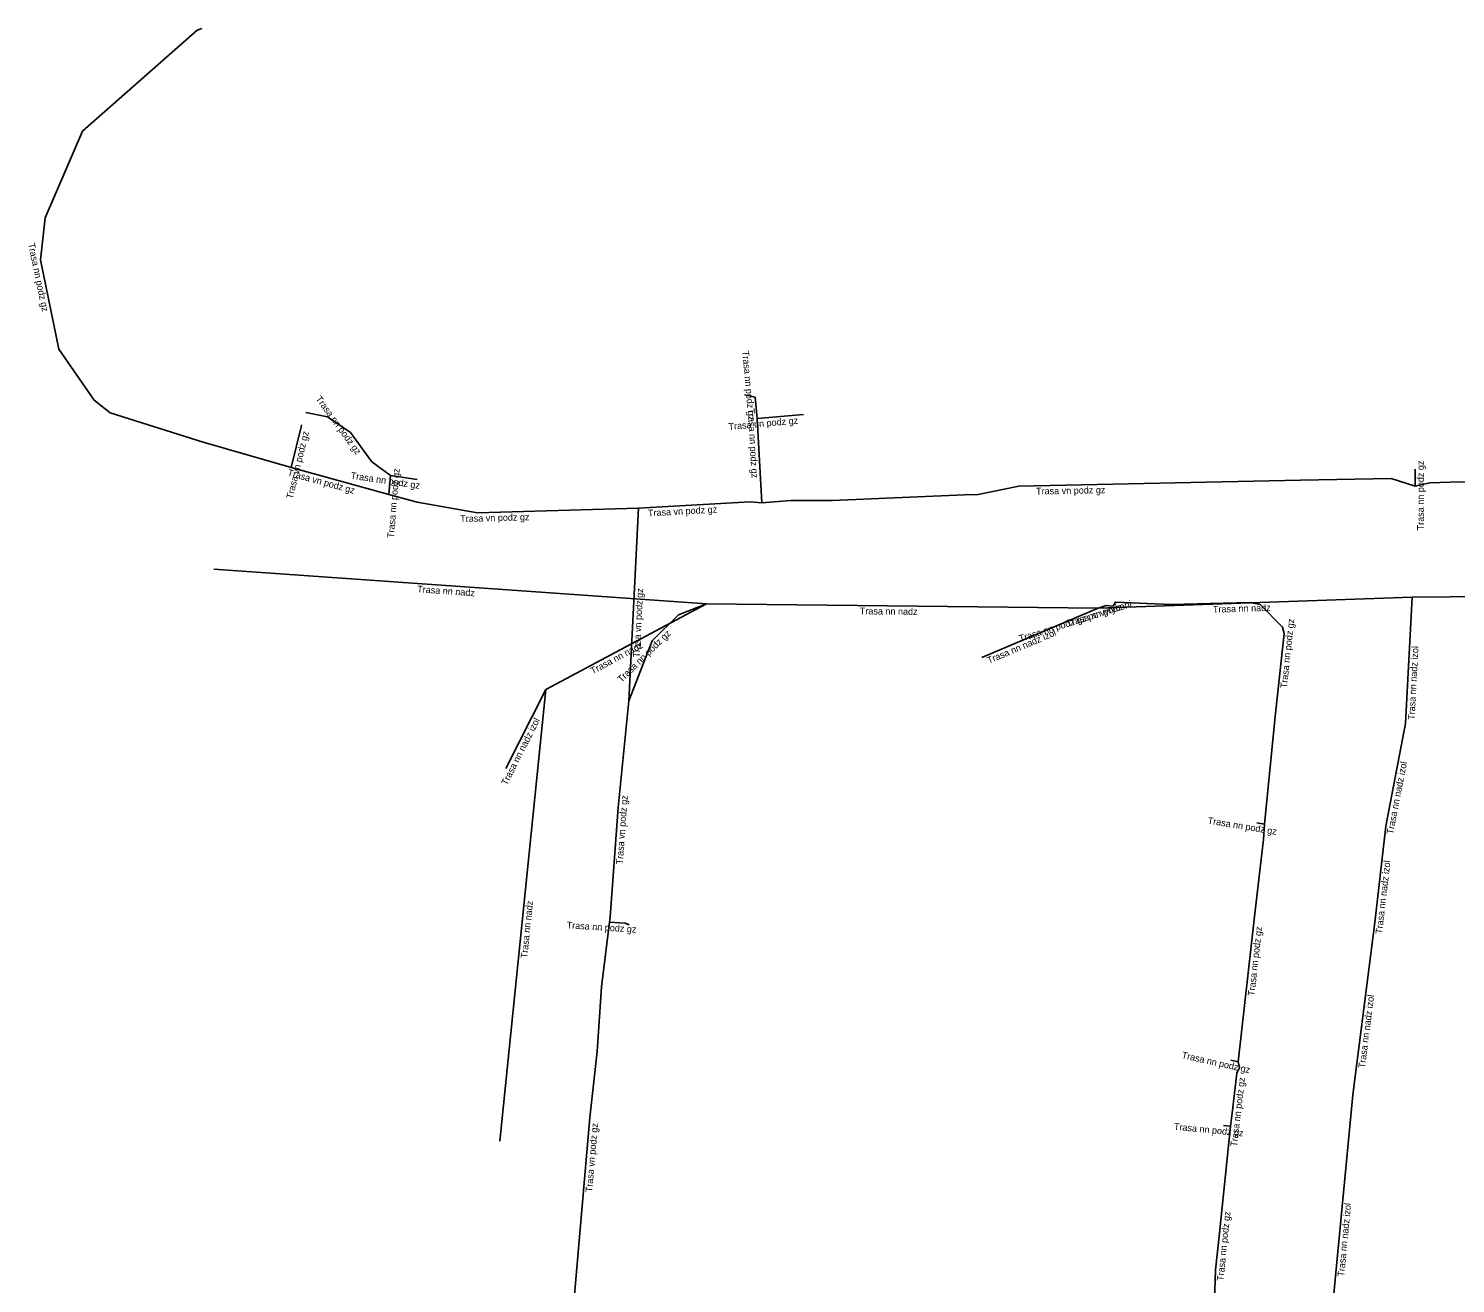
# Model space of a CAD drawing. Extents: x -772942 to -772530, y -1033745 to -1033298.
# Drawn here: x -772776.3 to -772670.7, y -1033402.1 to -1033309.2 of the extents above; entities that cross this region are included whole.
import ezdxf

# ---------------------------------------------------------------- set-up
doc = ezdxf.new("R2010")
doc.units = 0
for name, color, linetype in [('Popiskový text - Ostatní atributy Trasy', 7, 'Continuous'), ('Spojnice NN', 7, 'Continuous'), ('Spojnice VN', 7, 'Continuous')]:
    doc.layers.add(name, color=color, linetype=linetype)

msp = doc.modelspace()

# ---------------------------------------------------------------- linework, layer by layer
at = {"layer": 'Spojnice NN'}
for points in [[(-772756.83, -1033341.72), (-772763.36, -1033339.83), (-772770.24, -1033337.68), (-772771.43, -1033336.73), (-772774.03, -1033332.96), (-772775.4, -1033326.36), (-772775.05, -1033323.25), (-772772.27, -1033316.82), (-772763.8, -1033309.35), (-772763.46, -1033309.23)], [(-772722.36, -1033338.1), (-772722.51, -1033336.52), (-772723.29, -1033336.35)], [(-772749.5, -1033342.32), (-772750.87, -1033341.3), (-772752.45, -1033339.13), (-772754.15, -1033337.97), (-772755.76, -1033337.64)], [(-772722.36, -1033338.1), (-772718.93, -1033337.79)], [(-772722.01, -1033344.32), (-772722.36, -1033338.1)], [(-772749.5, -1033342.32), (-772749.61, -1033343.7)], [(-772747.53, -1033342.61), (-772749.5, -1033342.32)], [(-772673.68, -1033343.11), (-772673.68, -1033341.85)], [(-772762.57, -1033349.25), (-772726.12, -1033351.81)], [(-772726.12, -1033351.81), (-772738.01, -1033358.15)], [(-772731.86, -1033358.99), (-772730.14, -1033354.54), (-772728.18, -1033352.61), (-772726.12, -1033351.81)], [(-772726.12, -1033351.81), (-772697.12, -1033352.12)], [(-772697.12, -1033352.12), (-772673.89, -1033351.31)], [(-772684.83, -1033368.1), (-772684.03, -1033360.15), (-772683.38, -1033354), (-772683.48, -1033353.53), (-772685.15, -1033351.85), (-772685.91, -1033351.7), (-772691.73, -1033351.86), (-772695.85, -1033351.68), (-772696.01, -1033351.99)], [(-772674.39, -1033360.65), (-772673.89, -1033351.31)], [(-772656.87, -1033351.16), (-772673.89, -1033351.31)], [(-772705.74, -1033355.77), (-772697.12, -1033352.12)], [(-772696.01, -1033351.99), (-772696.55, -1033351.94), (-772697.12, -1033352.12)], [(-772696.01, -1033351.99), (-772696.55, -1033351.94), (-772697.12, -1033352.12)], [(-772741.4, -1033391.57), (-772738.01, -1033358.15)], [(-772740.96, -1033363.99), (-772738.01, -1033358.15)], [(-772675.85, -1033368.26), (-772674.39, -1033360.65)], [(-772686.77, -1033385.7), (-772685.57, -1033374.95), (-772684.89, -1033369.25), (-772684.83, -1033368.1)], [(-772684.83, -1033368.1), (-772685.38, -1033368.01)], [(-772675.85, -1033368.26), (-772676.67, -1033375.38)], [(-772731.84, -1033375.57), (-772732.12, -1033375.44), (-772733.28, -1033375.37)], [(-772676.67, -1033375.38), (-772678.29, -1033388.13)], [(-772686.77, -1033385.7), (-772687.31, -1033385.58)], [(-772687.35, -1033390.47), (-772687.22, -1033389.5), (-772686.87, -1033386.54), (-772686.67, -1033386.13), (-772686.77, -1033385.7)], [(-772678.29, -1033388.13), (-772680.02, -1033406.23)], [(-772688.86, -1033405.5), (-772688.56, -1033404.11), (-772688.44, -1033401.09), (-772688.15, -1033398.38), (-772687.35, -1033390.47)], [(-772687.35, -1033390.47), (-772687.85, -1033390.42)]]:
    msp.add_lwpolyline(points, dxfattribs=at)
at = {"layer": 'Spojnice VN'}
for points in [[(-772756.07, -1033338.57), (-772756.08, -1033338.6), (-772756.83, -1033341.72), (-772756.83, -1033341.72)], [(-772756.83, -1033341.72), (-772749.61, -1033343.71)], [(-772673.68, -1033343.11), (-772675.44, -1033342.54), (-772682.16, -1033342.66), (-772703, -1033343.09), (-772706.02, -1033343.72), (-772707.01, -1033343.75), (-772711.06, -1033343.91), (-772716.78, -1033344.17), (-772719.86, -1033344.16), (-772722.01, -1033344.32)], [(-772653.98, -1033342.55), (-772656.49, -1033342.79), (-772667.38, -1033342.84), (-772668.15, -1033342.81), (-772668.72, -1033342.83), (-772670.34, -1033342.77), (-772672.58, -1033342.84), (-772673.68, -1033343.11)], [(-772749.61, -1033343.71), (-772747.51, -1033344.28), (-772743.06, -1033345.07), (-772731.15, -1033344.73)], [(-772722.01, -1033344.32), (-772722.88, -1033344.26), (-772731.15, -1033344.73)], [(-772731.15, -1033344.73), (-772731.86, -1033358.99)], [(-772731.86, -1033358.99), (-772732.65, -1033366.88), (-772733.25, -1033374.96), (-772733.28, -1033375.37)], [(-772733.28, -1033375.37), (-772733.87, -1033380.14), (-772734.2, -1033384.94), (-772734.75, -1033389.83), (-772736.27, -1033407.5)]]:
    msp.add_lwpolyline(points, dxfattribs=at)

# ---------------------------------------------------------------- texts
at = {"layer": 'Popiskový text - Ostatní atributy Trasy'}
for s, rotation, p in [('Trasa nn podz gz', 281.735, (-772776.31, -1033325.16)), ('Trasa nn podz gz', 275.1715, (-772723.47, -1033333.1)), ('Trasa nn podz gz', 306.0681, (-772755.06, -1033336.64)), ('Trasa nn podz gz', 5.2155, (-772724.46, -1033338.94)), ('Trasa nn podz gz', 273.238, (-772723.06, -1033337.36)), ('Trasa vn podz gz', 76.4266, (-772756.73, -1033344.08)), ('Trasa nn podz gz', 90, (-772673.03, -1033346.37)), ('Trasa vn podz gz', 344.6401, (-772757.15, -1033342.31)), ('Trasa nn podz gz', 351.5519, (-772752.46, -1033342.54)), ('Trasa nn podz gz', 85.1951, (-772749.24, -1033346.95)), ('Trasa vn podz gz', 1.1875, (-772701.72, -1033343.72)), ('Trasa vn podz gz', 1.6248, (-772744.33, -1033345.76)), ('Trasa vn podz gz', 3.2701, (-772730.43, -1033345.34)), ('Trasa nn nadz', 355.9859, (-772747.53, -1033350.95)), ('Trasa vn podz gz', 87.1338, (-772731.05, -1033355.79)), ('Trasa nn podz gz po vytyceni', 17.5256, (-772702.9, -1033354.63)), ('Trasa nn podz', 17.5256, (-772699.38, -1033353.52)), ('Trasa nn nadz', 1.9968, (-772688.63, -1033352.47)), ('Trasa nn nadz', 359.3776, (-772714.77, -1033352.58)), ('Trasa nn podz gz', 44.4415, (-772732.4, -1033357.66)), ('Trasa nn nadz izol', 22.9137, (-772705.22, -1033356.25)), ('Trasa nn podz gz', 83.9667, (-772683.16, -1033358.07)), ('Trasa nn nadz', 28.0845, (-772734.53, -1033357.03)), ('Trasa nn nadz izol', 86.9367, (-772673.72, -1033360.4)), ('Trasa nn nadz izol', 63.2177, (-772740.88, -1033365.28)), ('Trasa nn nadz izol', 79.1008, (-772675.31, -1033368.89)), ('Trasa vn podz gz', 85.7743, (-772732.31, -1033371.1)), ('Trasa nn podz gz', 350.7067, (-772689.05, -1033368.07)), ('Trasa nn nadz izol', 83.4507, (-772676.12, -1033376.25)), ('Trasa nn nadz', 84.2039, (-772739.37, -1033378.05)), ('Trasa nn podz gz', 356.4237, (-772736.47, -1033375.82)), ('Trasa nn podz gz', 83.6306, (-772685.57, -1033380.84)), ('Trasa nn nadz izol', 82.7688, (-772677.39, -1033386.19)), ('Trasa nn podz gz', 347.3597, (-772690.98, -1033385.42)), ('Trasa nn podz gz', 83.2565, (-772686.86, -1033392)), ('Trasa vn podz gz', 85.077, (-772734.57, -1033395.36)), ('Trasa nn podz gz', 354.4361, (-772691.54, -1033390.72)), ('Trasa nn nadz izol', 84.534, (-772678.93, -1033401.61)), ('Trasa nn podz gz', 84.2249, (-772687.86, -1033401.93))]:
    msp.add_text(s, height=0.5, rotation=rotation, dxfattribs=at).set_placement(p)

doc.saveas('drawing.dxf')
